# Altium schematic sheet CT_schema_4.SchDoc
size 400 x 269 mm
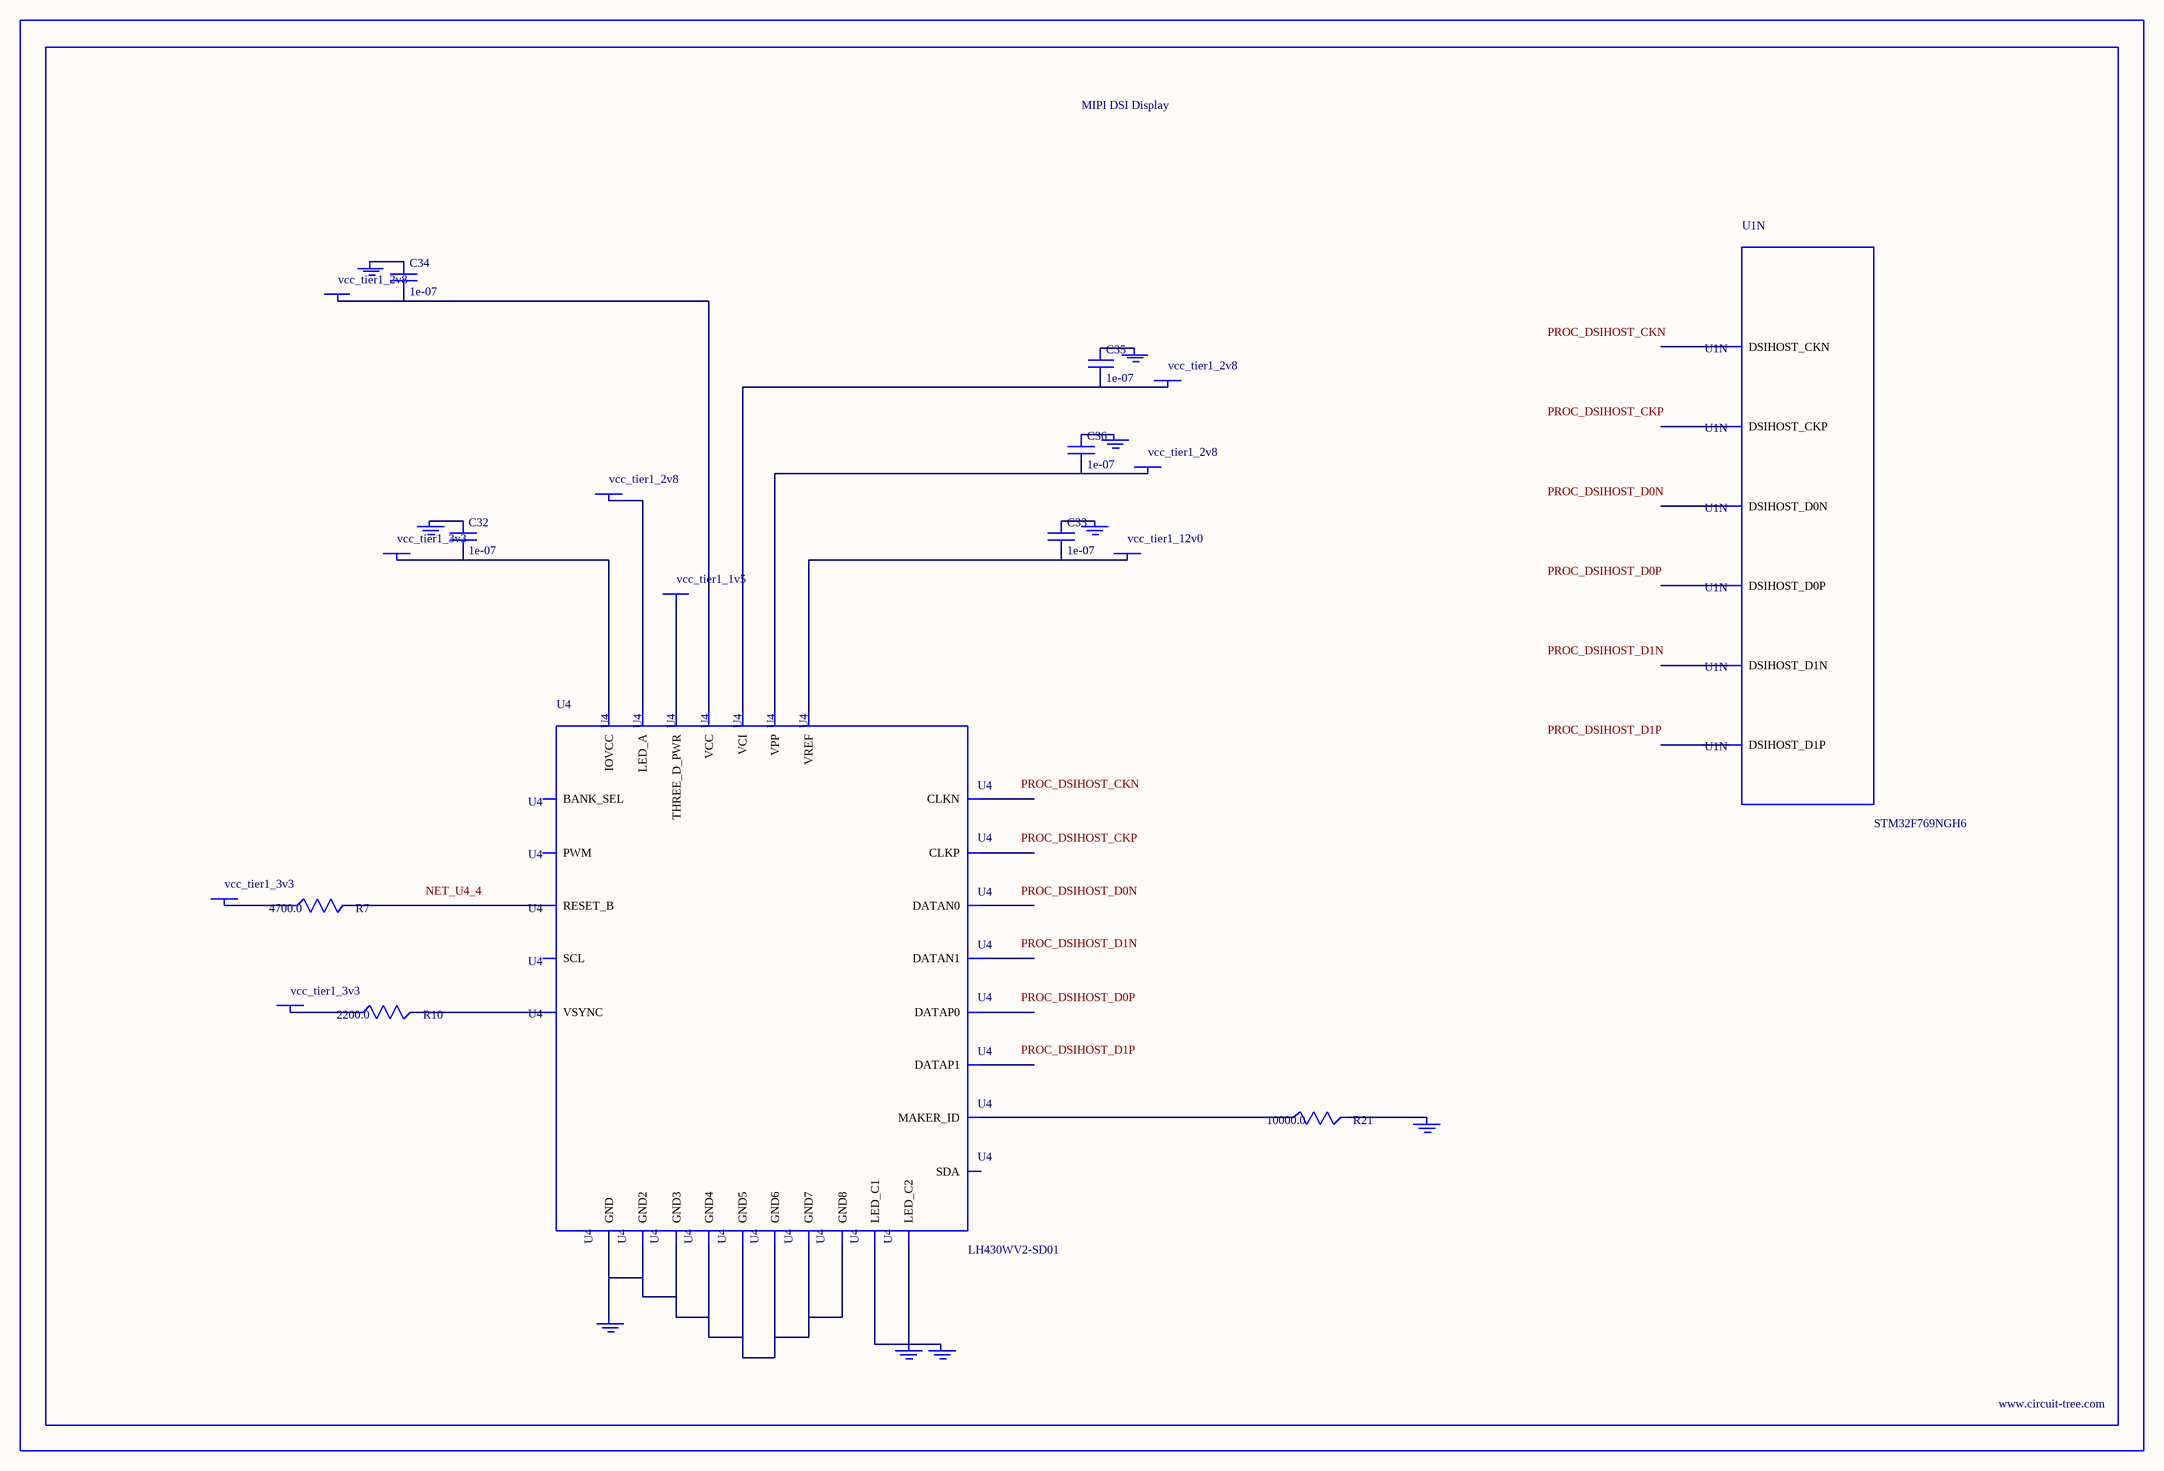
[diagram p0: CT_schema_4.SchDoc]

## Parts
BORDER3  (no value)
C32  1e-07  [C0402]
C33  1e-07  [C0402]
C34  1e-07  [C0402]
C35  1e-07  [C0402]
C36  1e-07  [C0402]
GND_INSTANCE_3_0  (no value)
GND_INSTANCE_3_1  (no value)
GND_INSTANCE_3_2  (no value)
GND_INSTANCE_3_3  (no value)
GND_INSTANCE_3_4  (no value)
GND_INSTANCE_3_5  (no value)
GND_INSTANCE_3_6  (no value)
GND_INSTANCE_3_7  (no value)
GND_INSTANCE_3_8  (no value)
POWER_INSTANCE_3_0  vcc_tier1_3v3
POWER_INSTANCE_3_1  vcc_tier1_2v8
POWER_INSTANCE_3_2  vcc_tier1_2v8
POWER_INSTANCE_3_3  vcc_tier1_2v8
POWER_INSTANCE_3_4  vcc_tier1_2v8
POWER_INSTANCE_3_5  vcc_tier1_12v0
POWER_INSTANCE_3_6  vcc_tier1_3v3
POWER_INSTANCE_3_7  vcc_tier1_3v3
POWER_INSTANCE_3_8  vcc_tier1_1v5
R7  4700.0  [R0603]
R10  2200.0  [R0603]
R21  10000.0  [R0603]
U1  STM32F769NGH6  [TFBGA216]  (part N of 17)
U4  LH430WV2-SD01  [LH430WV2-SD01]

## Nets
NetC32_1: C32.1 GND_INSTANCE_3_0.0(GND)
NetC32_2: C32.2 POWER_INSTANCE_3_0.0(PWR) U4.2(IOVCC)
NetC33_1: C33.1 GND_INSTANCE_3_7.0(GND)
NetC33_2: C33.2 POWER_INSTANCE_3_5.0(PWR) U4.30(VREF)
NetC34_1: C34.1 GND_INSTANCE_3_5.0(GND)
NetC34_2: C34.2 POWER_INSTANCE_3_3.0(PWR) U4.22(VCC)
NetC35_1: C35.1 GND_INSTANCE_3_4.0(GND)
NetC35_2: C35.2 POWER_INSTANCE_3_2.0(PWR) U4.21(VCI)
NetC36_1: C36.1 GND_INSTANCE_3_6.0(GND)
NetC36_2: C36.2 POWER_INSTANCE_3_4.0(PWR) U4.23(VPP)
NetGND_INSTANCE_3_1_0: GND_INSTANCE_3_1.0(GND) GND_INSTANCE_3_2.0(GND) U4.17(LED_C1) U4.18(LED_C2)
NetGND_INSTANCE_3_3_0: GND_INSTANCE_3_3.0(GND) R21.2
NetGND_INSTANCE_3_8_0: GND_INSTANCE_3_8.0(GND) U4.1(GND) U4.6(GND2) U4.9(GND3) U4.12(GND4) U4.15(GND5) U4.19(GND6) U4.24(GND7) U4.27(GND8)
NetPOWER_INSTANCE_3_1_0: POWER_INSTANCE_3_1.0(PWR) U4.16(LED_A)
NetPOWER_INSTANCE_3_6_0: POWER_INSTANCE_3_6.0(PWR) R7.1
NetPOWER_INSTANCE_3_7_0: POWER_INSTANCE_3_7.0(PWR) R10.1
NetPOWER_INSTANCE_3_8_0: POWER_INSTANCE_3_8.0(PWR) U4.29(THREE_D_PWR)
NetR7_2: R7.2 U4.4(RESET_B)
NetR10_2: R10.2 U4.5(VSYNC)
NetR21_1: R21.1 U4.20(MAKER_ID)

Not connected (* = marked no-connect by the designer): U1 F12(DSIHOST_D1P) F13(DSIHOST_D1N) H12(DSIHOST_CKP) H13(DSIHOST_CKN) J12(DSIHOST_D0P) J13(DSIHOST_D0N); U4 3(PWM) 7(DATAN0) 8(DATAP0) 10(DATAN1) 11(DATAP1) 13(CLKN) 14(CLKP) 25(SCL) 26(SDA) 28(BANK_SEL)

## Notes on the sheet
- Labels drawn without touching a wire or pin: NET_U4_4, PROC_DSIHOST_CKN, PROC_DSIHOST_CKP, PROC_DSIHOST_D0N, PROC_DSIHOST_D0P, PROC_DSIHOST_D1N, PROC_DSIHOST_D1P

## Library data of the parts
BORDER3 = BORDER_PAGE3
C32-C36 = C0402C104K3RACTU
GND_INSTANCE_3_0-GND_INSTANCE_3_8 = GND
POWER_INSTANCE_3_0-POWER_INSTANCE_3_8 = PWR
R7 = RC0603JR-074K7L
R10 = RC0603JR-072K2L
R21 = RC0603JR-0710KL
